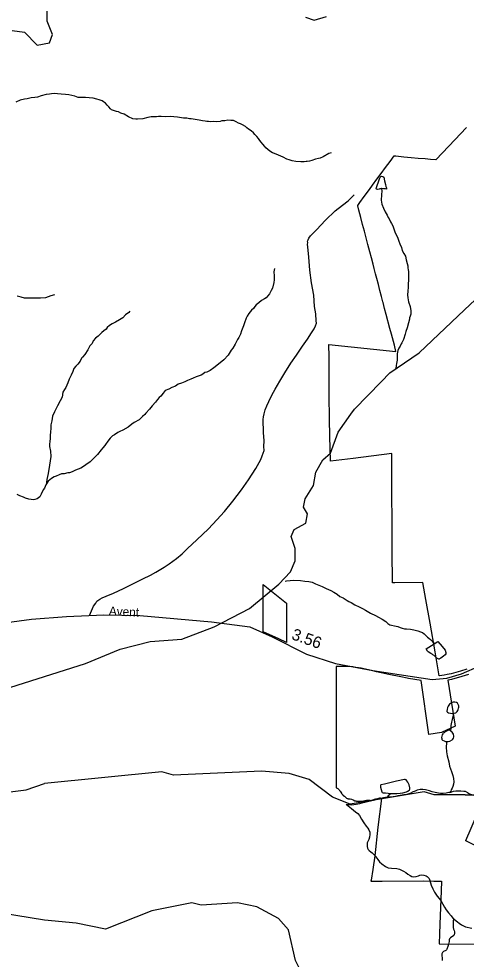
# Model space of a CAD drawing. Extents: x 2001466 to 2224147, y 644118 to 847247.
# Drawn here: x 2032407 to 2037237, y 678885 to 689045 of the extents above; entities that cross this region are included whole.
import ezdxf

# ---------------------------------------------------------------- set-up
doc = ezdxf.new("R2010")
doc.units = 0
for name, color, linetype in [('Exist Boundary Political City Limit New', 7, 'Continuous'), ('Exist Hydrographic Creek Single Shore', 7, 'Continuous'), ('Exist Hydrographic Misc Water Feature', 7, 'Continuous'), ('Exist Road Non-System Type 51', 7, 'Continuous'), ('Exist Road Secondary Mileage Hundredths English Label', 7, 'Continuous'), ('Exist Road Secondary Type 51 Attributed', 7, 'Continuous'), ('Exist Road Secondary Type 51 Label', 7, 'Continuous'), ('Map Preparation Boundary City Limit Buffer Line', 7, 'Continuous')]:
    doc.layers.add(name, color=color, linetype=linetype)

msp = doc.modelspace()

# ---------------------------------------------------------------- linework, layer by layer
at = {"layer": 'Exist Boundary Political City Limit New'}
for points in [[(2036252, 686317), (2036245, 686346), (2036232, 686393), (2036215, 686461), (2036197, 686528), (2036177, 686605), (2036157, 686680), (2036138, 686752), (2036119, 686824), (2036100, 686899), (2036079, 686979), (2036067, 687024), (2036066, 687029), (2036088, 687059), (2036137, 687126), (2036192, 687199), (2036227, 687248), (2036274, 687312), (2036320, 687374), (2036367, 687437), (2036416, 687503), (2036461, 687564), (2036477, 687563), (2036563, 687555), (2036643, 687548), (2036718, 687541), (2036793, 687534), (2036851, 687529), (2036911, 687524), (2036914, 687524), (2037116, 687737), (2037242, 687869)], [(2037243, 682019), (2037175, 681996), (2037076, 681968), (2037032, 681959), (2037000, 681953), (2036950, 681947), (2036947, 681947), (2036902, 682206), (2036847, 682517), (2036802, 682770), (2036769, 682954), (2036466, 682950), (2036441, 682950), (2036439, 683295), (2036437, 683616), (2036436, 683904), (2036434, 684350), (2036016, 684294), (2035774, 684264), (2035767, 684534), (2035764, 684557), (2035763, 684697), (2035758, 685000), (2035759, 685050), (2035758, 685201), (2035757, 685292), (2035757, 685392), (2035755, 685525), (2036479, 685450), (2036462, 685518), (2036431, 685636), (2036414, 685700), (2036374, 685851), (2036357, 685916), (2036340, 685981), (2036339, 685986), (2036323, 686045), (2036306, 686110), (2036290, 686175), (2036273, 686240), (2036260, 686289), (2036252, 686317)], [(2035297, 682733), (2035298, 682308), (2035214, 682345), (2035047, 682422), (2035047, 682934), (2035297, 682733)], [(2037263, 681962), (2037192, 681938), (2037156, 681928), (2037091, 681910), (2037078, 681907), (2037044, 681900), (2037039, 681899), (2037117, 681404), (2036971, 681334), (2036833, 681314), (2036751, 681895), (2036614, 681917), (2036599, 681920), (2036533, 681934), (2036404, 681961), (2036271, 681990), (2036216, 682003), (2036134, 682021), (2036102, 682028), (2036076, 682033), (2036046, 682038), (2036014, 682042), (2035981, 682046), (2035951, 682048), (2035924, 682048), (2035888, 682047), (2035848, 682047), (2035832, 682048)], [(2035832, 682048), (2035832, 681822), (2035834, 681162), (2035835, 680738), (2035839, 680737), (2035844, 680734), (2035850, 680730), (2035860, 680722), (2035866, 680715), (2035871, 680709), (2035878, 680700), (2035885, 680690), (2035891, 680679), (2035893, 680674), (2035895, 680670), (2035898, 680666), (2035905, 680659), (2035907, 680657), (2035923, 680646), (2035932, 680639), (2035938, 680632), (2035945, 680626), (2035953, 680622), (2035959, 680620), (2035962, 680619)], [(2035962, 680619), (2035965, 680619), (2035970, 680619), (2035984, 680617), (2036001, 680612), (2036018, 680605), (2036035, 680597), (2036046, 680594), (2036054, 680592), (2036068, 680591), (2036076, 680591), (2036086, 680591), (2036098, 680592), (2036112, 680593), (2036163, 680603), (2036170, 680604), (2036179, 680603), (2036198, 680602), (2036208, 680601), (2036220, 680603), (2036239, 680611), (2036249, 680615), (2036252, 680615), (2036262, 680616), (2036268, 680616), (2036272, 680617), (2036293, 680626), (2036306, 680628), (2036309, 680627), (2036316, 680625), (2036321, 680622), (2036323, 680620), (2036282, 680310), (2036250, 680000), (2036228, 679853), (2036211, 679739), (2036209, 679728), (2036210, 679728), (2036331, 679728), (2036777, 679730), (2036887, 679729), (2036971, 679727), (2036969, 679624), (2036952, 679262), (2036949, 679160), (2036945, 679050), (2037709, 679048)], [(2037336, 680113), (2037234, 680165), (2037234, 680166), (2037360, 680458)]]:
    msp.add_lwpolyline(points, dxfattribs=at)
at = {"layer": 'Exist Hydrographic Creek Single Shore'}
for points in [[(2032337, 688918), (2032470, 688902), (2032604, 688759), (2032737, 688786), (2032770, 688877), (2032712, 689019), (2032712, 689160)], [(2035503, 689061), (2035595, 689029), (2035728, 689069)], [(2029909, 680524), (2029977, 680557), (2030044, 680690), (2030219, 680831), (2030644, 680980), (2030752, 680974), (2030869, 680897), (2030968, 680931), (2031177, 681205), (2031568, 681624), (2031751, 681699), (2032243, 681800), (2033126, 682081), (2033501, 682234), (2033826, 682316), (2034167, 682342), (2034518, 682477)], [(2037226, 680659), (2037424, 680662), (2037574, 680721), (2037682, 680804), (2037765, 680983)], [(2037226, 680659), (2036893, 680659), (2036785, 680694), (2035985, 680560), (2035793, 680636), (2035543, 680825), (2035326, 680891), (2035026, 680917), (2034076, 680874), (2033951, 680909), (2032685, 680784)], [(2029909, 679059), (2030111, 679439), (2030178, 679497), (2030211, 679663), (2030269, 679774), (2030403, 679915), (2030802, 680114), (2031002, 680300), (2031210, 680365), (2031544, 680433), (2031777, 680557), (2032094, 680616), (2032227, 680682), (2032485, 680716), (2032685, 680784)]]:
    msp.add_lwpolyline(points, dxfattribs=at)
at = {"layer": 'Exist Hydrographic Misc Water Feature'}
for points in [[(2032760, 688236), (2032740, 688232), (2032702, 688226), (2032650, 688212), (2032610, 688200), (2032580, 688194), (2032542, 688190), (2032498, 688182), (2032468, 688178), (2032422, 688166), (2032376, 688144)], [(2035778, 687596), (2035754, 687588), (2035692, 687554), (2035662, 687540), (2035644, 687536), (2035612, 687528), (2035572, 687514), (2035546, 687506), (2035522, 687504), (2035510, 687502), (2035488, 687500), (2035452, 687498), (2035398, 687502), (2035358, 687512), (2035328, 687522), (2035300, 687530), (2035260, 687550), (2035236, 687562), (2035212, 687570), (2035168, 687588), (2035146, 687596), (2035116, 687616), (2035076, 687652), (2035064, 687666), (2035042, 687692), (2035024, 687712), (2035010, 687730), (2034994, 687750), (2034976, 687774), (2034956, 687796), (2034942, 687812), (2034916, 687836), (2034888, 687852), (2034868, 687868), (2034856, 687880), (2034822, 687900), (2034802, 687910), (2034780, 687918), (2034754, 687932), (2034724, 687946), (2034696, 687948), (2034664, 687951), (2034632, 687943), (2034600, 687941), (2034582, 687937), (2034540, 687933), (2034512, 687935), (2034474, 687933), (2034456, 687935), (2034436, 687937), (2034418, 687939), (2034392, 687941), (2034356, 687949), (2034310, 687957), (2034268, 687963), (2034250, 687965), (2034222, 687971), (2034184, 687973), (2034122, 687983), (2034082, 687985), (2034046, 687991), (2033990, 687987), (2033944, 687989), (2033916, 687989), (2033894, 687987), (2033876, 687987), (2033836, 687985), (2033800, 687979), (2033746, 687963), (2033688, 687959), (2033672, 687961), (2033638, 687965), (2033590, 687987), (2033546, 688013), (2033508, 688025), (2033482, 688039), (2033462, 688043), (2033442, 688049), (2033408, 688063), (2033398, 688073), (2033378, 688093), (2033362, 688113), (2033342, 688133), (2033332, 688139), (2033322, 688149), (2033308, 688157), (2033274, 688169), (2033250, 688177), (2033210, 688186), (2033168, 688190), (2033126, 688196), (2033076, 688196), (2033050, 688196), (2033012, 688208), (2032948, 688222), (2032910, 688228), (2032866, 688230), (2032824, 688234), (2032794, 688238), (2032760, 688236)], [(2036324, 687211), (2036318, 687209), (2036306, 687207), (2036298, 687205), (2036280, 687199), (2036270, 687203), (2036264, 687213), (2036276, 687245), (2036290, 687283), (2036300, 687315), (2036308, 687333), (2036318, 687345), (2036324, 687345), (2036338, 687341), (2036348, 687333), (2036354, 687295), (2036366, 687253), (2036370, 687233), (2036376, 687219), (2036376, 687205), (2036366, 687207), (2036346, 687209), (2036328, 687211), (2036324, 687211)], [(2036324, 687211), (2036326, 687187), (2036324, 687143), (2036320, 687085), (2036328, 687041), (2036346, 686999), (2036364, 686959), (2036384, 686925), (2036396, 686899), (2036406, 686883), (2036420, 686851), (2036432, 686833), (2036446, 686807), (2036456, 686777), (2036472, 686733), (2036488, 686701), (2036498, 686675), (2036512, 686643), (2036520, 686615), (2036540, 686575), (2036548, 686541), (2036566, 686511), (2036582, 686481), (2036588, 686441), (2036600, 686403), (2036606, 686375), (2036606, 686355), (2036610, 686333), (2036614, 686313), (2036614, 686277), (2036614, 686219), (2036612, 686185), (2036612, 686145), (2036608, 686101), (2036603, 686061), (2036607, 686029), (2036616, 685987), (2036631, 685937), (2036641, 685889), (2036639, 685855), (2036633, 685831), (2036625, 685815), (2036625, 685799), (2036613, 685759), (2036601, 685707), (2036587, 685667), (2036579, 685637), (2036561, 685579), (2036541, 685545), (2036537, 685535), (2036523, 685507), (2036509, 685485), (2036501, 685463), (2036491, 685425), (2036493, 685387), (2036493, 685357), (2036485, 685321), (2036483, 685299), (2036483, 685285), (2036479, 685279), (2036477, 685269), (2036475, 685261)], [(2035167, 686346), (2035159, 686312), (2035163, 686268), (2035163, 686224), (2035161, 686196), (2035147, 686136), (2035133, 686108), (2035115, 686072), (2035097, 686052), (2035079, 686032), (2035059, 686018), (2035027, 686000), (2034999, 685978), (2034971, 685956), (2034955, 685936), (2034941, 685914), (2034921, 685896), (2034891, 685860), (2034873, 685832), (2034861, 685812), (2034843, 685760), (2034835, 685726), (2034813, 685672), (2034801, 685638), (2034783, 685600), (2034767, 685580), (2034743, 685530), (2034719, 685488), (2034699, 685464), (2034667, 685412), (2034621, 685360), (2034563, 685312), (2034513, 685274), (2034473, 685246), (2034439, 685228), (2034417, 685222), (2034393, 685206), (2034375, 685196), (2034323, 685176), (2034289, 685164), (2034263, 685150), (2034227, 685136), (2034199, 685124), (2034163, 685110), (2034128, 685096), (2034098, 685076), (2034058, 685060), (2034027, 685043), (2033987, 685029), (2033966, 685000), (2033940, 684969), (2033924, 684952), (2033906, 684931), (2033882, 684903), (2033848, 684863), (2033818, 684827), (2033780, 684785), (2033768, 684771), (2033744, 684747), (2033706, 684711), (2033654, 684683), (2033626, 684665), (2033588, 684633), (2033532, 684599), (2033498, 684585), (2033476, 684575), (2033440, 684551), (2033420, 684539), (2033394, 684513), (2033370, 684481), (2033342, 684445), (2033336, 684435), (2033314, 684409), (2033296, 684389), (2033258, 684339), (2033220, 684301), (2033176, 684257), (2033132, 684225), (2033104, 684209), (2033078, 684189), (2033050, 684179), (2033038, 684175), (2033014, 684163), (2032982, 684151), (2032954, 684141), (2032936, 684139), (2032896, 684129), (2032870, 684127), (2032842, 684117), (2032812, 684105), (2032790, 684095), (2032762, 684077), (2032726, 684049), (2032706, 684021)], [(2037221, 685899), (2037504, 686166), (2037753, 686324), (2037834, 686347)], [(2032791, 686061), (2032753, 686051), (2032695, 686031), (2032641, 686027), (2032581, 686026), (2032539, 686026), (2032517, 686026), (2032493, 686026), (2032469, 686028), (2032433, 686038), (2032391, 686050)], [(2033605, 685887), (2033595, 685873), (2033561, 685847), (2033529, 685813), (2033495, 685791), (2033453, 685769), (2033417, 685749), (2033385, 685731), (2033363, 685709), (2033349, 685691), (2033325, 685673), (2033303, 685655), (2033263, 685617), (2033237, 685593), (2033209, 685565), (2033199, 685537), (2033175, 685511), (2033153, 685469), (2033121, 685417), (2033096, 685389), (2033085, 685377), (2033069, 685347), (2033044, 685313), (2033024, 685293), (2033003, 685267), (2032992, 685235), (2032974, 685195), (2032952, 685151), (2032936, 685111), (2032914, 685063), (2032900, 685041), (2032884, 685011), (2032874, 684957), (2032854, 684919), (2032826, 684865), (2032806, 684827), (2032792, 684797), (2032772, 684751), (2032764, 684703), (2032754, 684659), (2032754, 684637), (2032752, 684617), (2032748, 684581), (2032746, 684543), (2032746, 684509), (2032742, 684477), (2032738, 684449), (2032740, 684423), (2032748, 684373), (2032752, 684315), (2032740, 684223), (2032724, 684131), (2032710, 684069), (2032708, 684037), (2032706, 684021)], [(2036318, 685121), (2036414, 685220), (2036730, 685436), (2037221, 685899)], [(2035993, 684773), (2036031, 684827), (2036318, 685121)], [(2035498, 683860), (2035590, 684003), (2035614, 684147), (2035689, 684280), (2035773, 684353), (2035856, 684578), (2035993, 684773)], [(2032706, 684021), (2032698, 684011), (2032684, 683973), (2032670, 683955), (2032648, 683909), (2032635, 683879), (2032606, 683857), (2032582, 683851), (2032563, 683847), (2032542, 683851), (2032514, 683855), (2032479, 683865), (2032457, 683875), (2032418, 683891), (2032388, 683905)], [(2034518, 682477), (2034899, 682672), (2035215, 682938), (2035340, 683070), (2035390, 683187), (2035390, 683321), (2035348, 683453), (2035382, 683528), (2035507, 683594), (2035523, 683696), (2035481, 683769), (2035498, 683860)], [(2035283, 682969), (2035299, 682971), (2035337, 682977), (2035377, 682979), (2035448, 682975), (2035495, 682969), (2035538, 682965), (2035576, 682957), (2035610, 682941), (2035645, 682927), (2035681, 682913), (2035727, 682889), (2035775, 682867), (2035809, 682849), (2035843, 682827), (2035875, 682805), (2035909, 682789), (2035951, 682759), (2035971, 682749), (2035995, 682737), (2036035, 682715), (2036081, 682693), (2036119, 682675), (2036149, 682655), (2036205, 682623), (2036260, 682599), (2036292, 682579), (2036329, 682559), (2036369, 682535), (2036393, 682513), (2036413, 682497), (2036482, 682482), (2036501, 682478)], [(2036501, 682478), (2036525, 682467), (2036547, 682461), (2036573, 682455), (2036593, 682454), (2036635, 682449), (2036671, 682443), (2036717, 682431), (2036744, 682421), (2036765, 682413), (2036783, 682401), (2036807, 682378), (2036821, 682365), (2036835, 682352), (2036851, 682338), (2036867, 682323), (2036879, 682310), (2036885, 682302), (2036891, 682292)], [(2036891, 682292), (2036931, 682318), (2036979, 682264), (2037009, 682222), (2037019, 682200), (2037019, 682184), (2037009, 682174), (2036991, 682157), (2036965, 682138), (2036951, 682130), (2036947, 682128), (2036943, 682128), (2036935, 682130), (2036922, 682138), (2036903, 682158), (2036879, 682174), (2036871, 682180), (2036855, 682187), (2036827, 682204), (2036820, 682211), (2036807, 682238), (2036891, 682292)], [(2037098, 681541), (2037108, 681542), (2037124, 681548), (2037140, 681560), (2037148, 681572), (2037152, 681583), (2037156, 681596), (2037158, 681608), (2037158, 681622), (2037152, 681638), (2037143, 681651), (2037134, 681658), (2037114, 681662), (2037098, 681660), (2037087, 681658), (2037076, 681654), (2037068, 681648), (2037059, 681639), (2037050, 681630), (2037044, 681620), (2037039, 681611), (2037036, 681604), (2037032, 681582), (2037030, 681566), (2037030, 681560), (2037036, 681554), (2037048, 681546), (2037068, 681542), (2037090, 681540), (2037098, 681541)], [(2037098, 681541), (2037096, 681522), (2037086, 681474), (2037080, 681444), (2037072, 681410), (2037070, 681376), (2037068, 681358), (2037068, 681351)], [(2037068, 681351), (2037056, 681358), (2037050, 681358), (2037038, 681356), (2037012, 681342), (2037006, 681338), (2036999, 681332), (2036990, 681326), (2036985, 681320), (2036979, 681308), (2036974, 681296), (2036972, 681280), (2036973, 681268), (2036975, 681258), (2036980, 681252), (2036999, 681244), (2037015, 681238), (2037029, 681238)], [(2037029, 681238), (2037043, 681238), (2037061, 681242), (2037085, 681254), (2037094, 681262), (2037101, 681272), (2037104, 681286), (2037104, 681294), (2037101, 681315), (2037094, 681326), (2037086, 681338), (2037076, 681346), (2037068, 681351)], [(2037029, 681238), (2037025, 681224), (2037023, 681176), (2037025, 681126), (2037033, 681082), (2037049, 681018), (2037059, 680970), (2037079, 680914), (2037093, 680868), (2037101, 680837), (2037103, 680802), (2037101, 680775), (2037095, 680752), (2037085, 680734), (2037077, 680716), (2037072, 680700), (2037060, 680687)], [(2036425, 680676), (2036436, 680675), (2036488, 680675), (2036524, 680677), (2036552, 680681), (2036592, 680693), (2036608, 680701), (2036624, 680716), (2036628, 680721), (2036630, 680738), (2036621, 680767), (2036607, 680797), (2036598, 680811), (2036588, 680823), (2036579, 680826), (2036571, 680827), (2036485, 680807), (2036357, 680777), (2036317, 680767), (2036314, 680761), (2036314, 680757), (2036314, 680745), (2036326, 680693), (2036332, 680687), (2036340, 680681), (2036366, 680681), (2036425, 680676)], [(2036384, 680635), (2036366, 680633), (2036346, 680629), (2036330, 680625), (2036303, 680618), (2036232, 680600), (2036156, 680582), (2036112, 680571), (2036084, 680564), (2036049, 680556), (2036024, 680552), (2036002, 680550), (2035982, 680551), (2035966, 680553), (2035945, 680555), (2035940, 680559)], [(2037060, 680687), (2037050, 680684), (2037022, 680680), (2036988, 680676), (2036960, 680676), (2036939, 680680), (2036901, 680686), (2036872, 680694), (2036840, 680702), (2036798, 680714), (2036769, 680718), (2036740, 680717), (2036708, 680711), (2036685, 680701), (2036656, 680688), (2036646, 680683), (2036628, 680675), (2036598, 680665), (2036566, 680659), (2036526, 680654), (2036498, 680648), (2036474, 680643), (2036450, 680639), (2036428, 680635), (2036408, 680635), (2036384, 680635)], [(2036425, 680676), (2036422, 680671), (2036408, 680659), (2036396, 680649), (2036384, 680635)], [(2037060, 680687), (2037084, 680694), (2037102, 680700), (2037127, 680705), (2037157, 680704), (2037180, 680703), (2037212, 680700), (2037227, 680699), (2037253, 680684), (2037273, 680672), (2037319, 680658), (2037347, 680654), (2037367, 680651), (2037387, 680649)], [(2035940, 680559), (2035945, 680555), (2035998, 680513), (2036044, 680476), (2036066, 680459), (2036084, 680437), (2036108, 680399), (2036132, 680359), (2036156, 680322), (2036174, 680301), (2036188, 680283), (2036199, 680259), (2036199, 680231), (2036193, 680203), (2036185, 680179), (2036169, 680142), (2036167, 680123), (2036167, 680101), (2036171, 680083), (2036179, 680071), (2036191, 680059), (2036209, 680043), (2036223, 680033), (2036241, 680017), (2036263, 679989), (2036285, 679961), (2036303, 679937), (2036325, 679915), (2036366, 679888), (2036395, 679873), (2036431, 679867), (2036487, 679864), (2036519, 679857), (2036559, 679835), (2036587, 679820), (2036609, 679805), (2036631, 679789), (2036651, 679777), (2036671, 679775), (2036697, 679777), (2036721, 679786), (2036737, 679792), (2036759, 679796), (2036781, 679794), (2036805, 679786), (2036817, 679778), (2036837, 679758), (2036845, 679734), (2036861, 679684), (2036877, 679646), (2036897, 679608), (2036924, 679564), (2036947, 679539), (2036968, 679510), (2037002, 679446), (2037020, 679418), (2037048, 679385), (2037074, 679355), (2037094, 679328), (2037099, 679323)], [(2035436, 678793), (2035394, 678869), (2035319, 679202), (2035211, 679325), (2034977, 679451), (2034769, 679492), (2034377, 679467), (2034277, 679492), (2033844, 679409), (2033344, 679209), (2033027, 679275), (2032686, 679308), (2032219, 679383), (2031903, 679356), (2031719, 679291), (2031569, 679183), (2031378, 679157), (2031261, 679107), (2030953, 679090), (2030836, 679122), (2030420, 679098), (2030170, 678982), (2029909, 678947)], [(2037099, 679323), (2037098, 679297), (2037096, 679265), (2037098, 679229), (2037102, 679208), (2037108, 679195), (2037110, 679181), (2037112, 679169), (2037112, 679160), (2037109, 679151), (2037104, 679142), (2037100, 679138), (2037084, 679125), (2037068, 679115), (2037059, 679106), (2037054, 679093), (2037052, 679076), (2037047, 679046), (2037041, 679021), (2037030, 678992), (2037026, 678985), (2037017, 678979), (2036993, 678967), (2036981, 678958), (2036974, 678944), (2036974, 678924), (2036977, 678896), (2036979, 678869)], [(2037099, 679323), (2037110, 679312), (2037142, 679290), (2037162, 679274), (2037186, 679256), (2037208, 679245), (2037229, 679234)], [(2037229, 679234), (2037299, 679219)]]:
    msp.add_lwpolyline(points, dxfattribs=at)
at = {"layer": 'Exist Road Non-System Type 51'}
msp.add_lwpolyline([(2033170, 682598), (2033215, 682700), (2033238, 682732), (2033250, 682752), (2033283, 682774), (2033308, 682790), (2033350, 682808), (2033428, 682840), (2033537, 682890), (2033646, 682943), (2033748, 682993), (2033830, 683033), (2033888, 683065), (2033978, 683119), (2034030, 683155), (2034110, 683213), (2034170, 683265), (2034230, 683321), (2034330, 683417), (2034454, 683533), (2034544, 683633), (2034628, 683721), (2034718, 683835), (2034812, 683957), (2034886, 684065), (2034968, 684187), (2035022, 684285), (2035036, 684323), (2035056, 684381), (2035054, 684425), (2035058, 684487), (2035050, 684577), (2035046, 684715), (2035050, 684743), (2035058, 684777), (2035068, 684819), (2035084, 684863), (2035106, 684909), (2035140, 684977), (2035174, 685043), (2035226, 685129), (2035280, 685219), (2035346, 685325), (2035407, 685411), (2035472, 685509), (2035525, 685585), (2035569, 685653), (2035595, 685697), (2035611, 685729), (2035621, 685757), (2035617, 685782), (2035613, 685859), (2035601, 685935), (2035591, 686059), (2035569, 686192), (2035551, 686331), (2035539, 686469), (2035527, 686581), (2035525, 686605), (2035529, 686629), (2035525, 686641), (2035533, 686657), (2035539, 686675), (2035555, 686699), (2035571, 686714), (2035621, 686764), (2035719, 686870), (2035823, 686970), (2035903, 687030), (2035963, 687078), (2036027, 687144)], dxfattribs=at)
at = {"layer": 'Exist Road Secondary Type 51 Attributed'}
msp.add_lwpolyline([(2032143, 682503), (2032544, 682560), (2032923, 682588), (2033324, 682605), (2033714, 682598), (2034486, 682531), (2034900, 682474), (2035141, 682368), (2035514, 682182), (2035825, 682081), (2036230, 682003), (2036631, 681941), (2036869, 681905), (2037029, 681922), (2037187, 681969), (2037384, 682053)], dxfattribs=at)
at = {"layer": 'Map Preparation Boundary City Limit Buffer Line'}
for points in [[(2036252, 686317), (2036245, 686346), (2036232, 686393), (2036215, 686461), (2036197, 686528), (2036177, 686605), (2036157, 686680), (2036138, 686752), (2036119, 686824), (2036100, 686899), (2036079, 686979), (2036067, 687024), (2036066, 687029), (2036088, 687059), (2036137, 687126), (2036192, 687199), (2036227, 687248), (2036274, 687312), (2036320, 687374), (2036367, 687437), (2036416, 687503), (2036461, 687564), (2036477, 687563), (2036563, 687555), (2036643, 687548), (2036718, 687541), (2036793, 687534), (2036851, 687529), (2036911, 687524), (2036914, 687524), (2037116, 687737), (2037242, 687869)], [(2037243, 682019), (2037175, 681996), (2037076, 681968), (2037032, 681959), (2037000, 681953), (2036950, 681947), (2036947, 681947), (2036902, 682206), (2036847, 682517), (2036802, 682770), (2036769, 682954), (2036466, 682950), (2036441, 682950), (2036439, 683295), (2036437, 683616), (2036436, 683904), (2036434, 684350), (2036016, 684294), (2035774, 684264), (2035767, 684534), (2035764, 684557), (2035763, 684697), (2035758, 685000), (2035759, 685050), (2035758, 685201), (2035757, 685292), (2035757, 685392), (2035755, 685525), (2036479, 685450), (2036462, 685518), (2036431, 685636), (2036414, 685700), (2036374, 685851), (2036357, 685916), (2036340, 685981), (2036339, 685986), (2036323, 686045), (2036306, 686110), (2036290, 686175), (2036273, 686240), (2036260, 686289), (2036252, 686317)], [(2035297, 682733), (2035298, 682308), (2035214, 682345), (2035047, 682422), (2035047, 682934), (2035297, 682733)], [(2037263, 681962), (2037192, 681938), (2037156, 681928), (2037091, 681910), (2037078, 681907), (2037044, 681900), (2037039, 681899), (2037117, 681404), (2036971, 681334), (2036833, 681314), (2036751, 681895), (2036614, 681917), (2036599, 681920), (2036533, 681934), (2036404, 681961), (2036271, 681990), (2036216, 682003), (2036134, 682021), (2036102, 682028), (2036076, 682033), (2036046, 682038), (2036014, 682042), (2035981, 682046), (2035951, 682048), (2035924, 682048), (2035888, 682047), (2035848, 682047), (2035832, 682048)], [(2035832, 682048), (2035832, 681822), (2035834, 681162), (2035835, 680738), (2035839, 680737), (2035844, 680734), (2035850, 680730), (2035860, 680722), (2035866, 680715), (2035871, 680709), (2035878, 680700), (2035885, 680690), (2035891, 680679), (2035893, 680674), (2035895, 680670), (2035898, 680666), (2035905, 680659), (2035907, 680657), (2035923, 680646), (2035932, 680639), (2035938, 680632), (2035945, 680626), (2035953, 680622), (2035959, 680620), (2035962, 680619)], [(2035962, 680619), (2035965, 680619), (2035970, 680619), (2035984, 680617), (2036001, 680612), (2036018, 680605), (2036035, 680597), (2036046, 680594), (2036054, 680592), (2036068, 680591), (2036076, 680591), (2036086, 680591), (2036098, 680592), (2036112, 680593), (2036163, 680603), (2036170, 680604), (2036179, 680603), (2036198, 680602), (2036208, 680601), (2036220, 680603), (2036239, 680611), (2036249, 680615), (2036252, 680615), (2036262, 680616), (2036268, 680616), (2036272, 680617), (2036293, 680626), (2036306, 680628), (2036309, 680627), (2036316, 680625), (2036321, 680622), (2036323, 680620), (2036282, 680310), (2036250, 680000), (2036228, 679853), (2036211, 679739), (2036209, 679728), (2036210, 679728), (2036331, 679728), (2036777, 679730), (2036887, 679729), (2036971, 679727), (2036969, 679624), (2036952, 679262), (2036949, 679160), (2036945, 679050), (2037709, 679048)], [(2037336, 680113), (2037234, 680165), (2037234, 680166), (2037360, 680458)]]:
    msp.add_lwpolyline(points, dxfattribs=at)

# ---------------------------------------------------------------- texts
at = {"layer": 'Exist Road Secondary Mileage Hundredths English Label'}
msp.add_text('3.56', height=125, rotation=340.307, dxfattribs=at).set_placement((2035343, 682345))
at = {"layer": 'Exist Road Secondary Type 51 Label'}
msp.add_text('Avent', height=95, rotation=356.8555, dxfattribs=at).set_placement((2033378, 682602))

doc.saveas('drawing.dxf')
